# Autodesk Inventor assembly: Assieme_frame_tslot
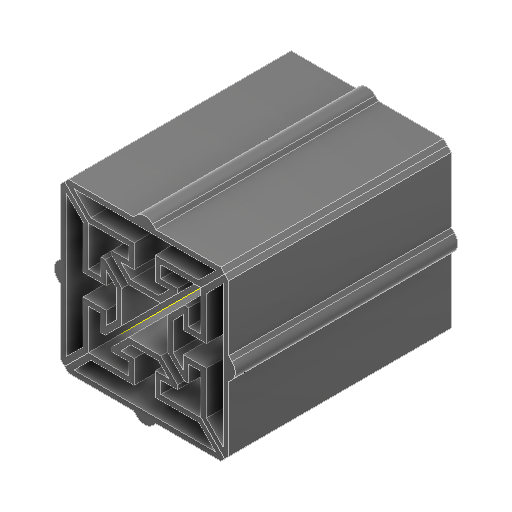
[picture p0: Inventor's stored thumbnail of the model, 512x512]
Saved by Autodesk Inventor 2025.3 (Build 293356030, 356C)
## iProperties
Created: 2026-03
Part Number: Assieme_frame_tslot
Document SubType Name: Assembly
Designer: R5800u
Author: R5800u
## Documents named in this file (2)
- C:\Users\R5800u\Desktop\robot_riduttore_cicloidale2\Workgroups\NotInProject\Assieme_frame_tslot.iam
- C:\Users\R5800u\Desktop\robot_riduttore_cicloidale2\Workgroups\NotInProject\frame_tslot.ipt
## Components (4 placed, 1 different names)
1. frame_tslot:1
2. frame_tslot:2
3. frame_tslot:3
4. frame_tslot:4
